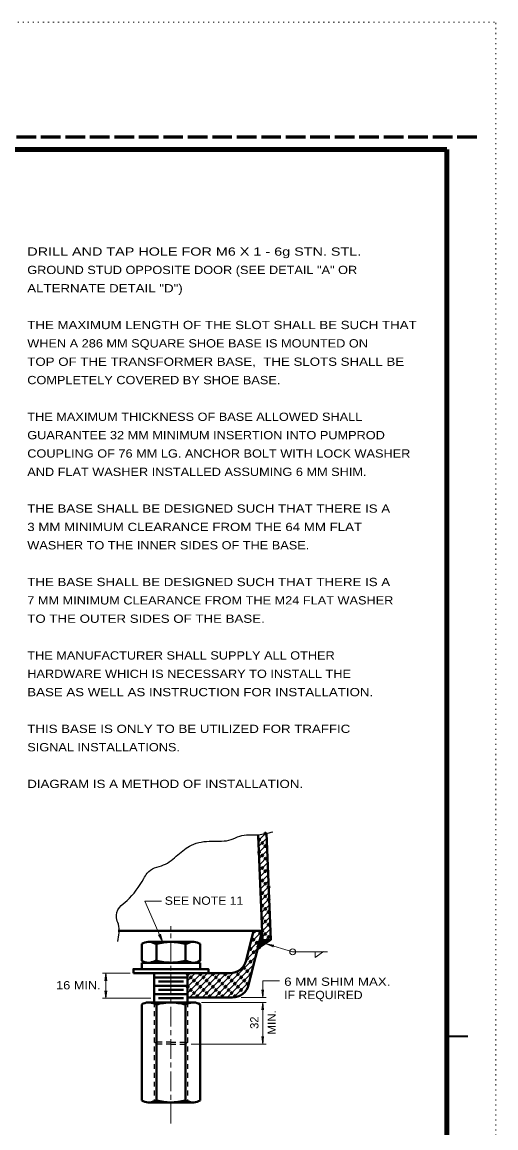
# Model space of a CAD drawing. Extents: x 312583 to 312854, y 144419 to 144597.
# Drawn here: x 312810 to 312853.5, y 144495.2 to 144596.8 of the extents above; entities that cross this region are included whole.
import ezdxf

# ---------------------------------------------------------------- set-up
doc = ezdxf.new("R2010")
doc.units = 0
doc.header["$LTSCALE"] = 0.3
doc.header["$PDMODE"] = 32
doc.header["$PDSIZE"] = 0.15
for name, pattern in [('DOTTED', [1.5, 0.3, -1.2]), ('LONG_DASH_SHORT_DASH', [9.9, 6, -1.2, 1.5, -1.2]), ('LONG_DASHED', [7.5, 6, -1.5]), ('SHORT_DASHED', [2.7, 1.5, -1.2])]:
    doc.linetypes.add(name, pattern=pattern)
for name, color, linetype, lineweight in [('1', 7, 'Continuous', 40), ('2', 7, 'Continuous', 13), ('62', 7, 'DOTTED', 13), ('63', 7, 'LONG_DASHED', 60)]:
    doc.layers.add(name, color=color, linetype=linetype, lineweight=lineweight)

msp = doc.modelspace()

# ---------------------------------------------------------------- linework, layer by layer
at = {"layer": '1', "lineweight": 158}
msp.add_line((312849, 144423.1446), (312849, 144585.0846), dxfattribs=at)
at = {"layer": '1'}
for p, q in [((312832.0464, 144512.4408), (312831.6554, 144522.0855)), ((312832.8131, 144512.4715), (312832.4144, 144522.2695)), ((312818.7984, 144513.2995), (312832.0234, 144513.2995)), ((312831.2338, 144513.2995), (312830.5438, 144510.5548)), ((312832.0234, 144513.2995), (312830.7814, 144508.3238)), ((312821.5431, 144512.2721), (312823.6438, 144512.2721)), ((312825.7368, 144512.2721), (312823.6438, 144512.2721)), ((312820.9604, 144512.0805), (312820.9604, 144510.5471)), ((312822.3021, 144512.0805), (312822.3021, 144510.5471)), ((312824.9778, 144512.0805), (312824.9778, 144510.5471)), ((312826.3271, 144512.0805), (312826.3271, 144510.5471)), ((312820.9604, 144509.7805), (312820.9604, 144510.3555)), ((312820.9604, 144510.3555), (312823.6438, 144510.3555)), ((312826.3271, 144510.3555), (312823.6438, 144510.3555)), ((312826.3271, 144509.7805), (312826.3271, 144510.3555)), ((312823.6438, 144509.3971), (312820.1938, 144509.3971)), ((312822.1104, 144509.3971), (312822.1104, 144506.7138)), ((312823.6438, 144509.3971), (312827.0938, 144509.3971)), ((312825.1771, 144509.3971), (312825.1771, 144506.7138)), ((312829.0564, 144509.3971), (312827.0938, 144509.3971)), ((312822.1104, 144509.0138), (312823.6438, 144509.0138)), ((312822.1104, 144508.2471), (312823.6438, 144508.2471)), ((312822.4938, 144508.6305), (312823.6438, 144508.6305)), ((312825.1771, 144509.0138), (312823.6438, 144509.0138)), ((312824.7938, 144508.6305), (312823.6438, 144508.6305)), ((312825.1771, 144508.2471), (312823.6438, 144508.2471)), ((312822.1104, 144507.4805), (312823.6438, 144507.4805)), ((312822.4938, 144507.8638), (312823.6438, 144507.8638)), ((312824.7938, 144507.8638), (312823.6438, 144507.8638)), ((312825.1771, 144507.4805), (312823.6438, 144507.4805)), ((312820.9604, 144506.5221), (312820.9604, 144497.7055)), ((312821.5431, 144506.7138), (312823.6438, 144506.7138)), ((312822.3021, 144506.5221), (312822.3021, 144497.7055)), ((312822.4938, 144507.0971), (312823.6438, 144507.0971)), ((312824.7938, 144507.0971), (312823.6438, 144507.0971)), ((312825.7368, 144506.7138), (312823.6438, 144506.7138)), ((312824.9778, 144506.5221), (312824.9778, 144497.7055)), ((312829.2941, 144507.1661), (312825.1771, 144507.1661)), ((312826.3271, 144506.5221), (312826.3271, 144497.7055)), ((312821.5431, 144497.5138), (312823.6438, 144497.5138)), ((312825.7368, 144497.5138), (312823.6438, 144497.5138))]:
    msp.add_line(p, q, dxfattribs=at)
at = {"layer": '1', "lineweight": 13}
for p, q in [((312831.6784, 144521.5795), (312832.3531, 144522.2541)), ((312831.7014, 144521.0275), (312832.4374, 144521.7635)), ((312831.7244, 144520.4755), (312832.4604, 144521.2115)), ((312831.7398, 144519.9235), (312832.4834, 144520.6595)), ((312831.7704, 144519.3638), (312832.5064, 144520.1075)), ((312831.7858, 144518.8118), (312832.5294, 144519.5478)), ((312831.8088, 144518.2521), (312832.5524, 144518.9958)), ((312831.8318, 144517.7001), (312832.5754, 144518.4361)), ((312831.8624, 144517.1481), (312832.5984, 144517.8841)), ((312831.8778, 144516.5961), (312832.6138, 144517.3321)), ((312831.9008, 144516.0365), (312832.6444, 144516.7801)), ((312831.9238, 144515.4845), (312832.6598, 144516.2281)), ((312831.9468, 144514.9325), (312832.6904, 144515.6685)), ((312831.9698, 144514.3728), (312832.7058, 144515.1165)), ((312831.9928, 144513.8208), (312832.7288, 144514.5568)), ((312831.1418, 144512.9468), (312831.4944, 144513.2995)), ((312832.0158, 144513.2688), (312832.7518, 144514.0048)), ((312832.0388, 144512.7168), (312832.7748, 144513.4528)), ((312830.7584, 144511.4135), (312831.8164, 144512.4715)), ((312830.9501, 144512.1801), (312832.0081, 144513.2381)), ((312832.3531, 144512.4485), (312832.7978, 144512.9008)), ((312830.5668, 144510.6391), (312831.6248, 144511.6971)), ((312827.6688, 144507.1661), (312831.4331, 144510.9305)), ((312825.1771, 144507.5495), (312827.0171, 144509.3971)), ((312825.1771, 144508.1321), (312826.4421, 144509.3971)), ((312825.1771, 144508.7071), (312825.8671, 144509.3971)), ((312825.1771, 144509.2821), (312825.2844, 144509.3971)), ((312825.3611, 144507.1661), (312827.5921, 144509.3971)), ((312825.9361, 144507.1661), (312828.1671, 144509.3971)), ((312826.5111, 144507.1661), (312828.7498, 144509.3971)), ((312827.0938, 144507.1661), (312829.3631, 144509.4355)), ((312828.2438, 144507.1661), (312831.2414, 144510.1561)), ((312828.8188, 144507.1661), (312831.0498, 144509.3895)), ((312829.4244, 144507.1891), (312830.8504, 144508.6228))]:
    msp.add_line(p, q, dxfattribs=at)
at = {"layer": '1', "linetype": 'LONG_DASH_SHORT_DASH', "lineweight": 13}
msp.add_line((312823.6438, 144495.5971), (312823.6438, 144513.7288), dxfattribs=at)
at = {"layer": '1', "lineweight": 25}
for p, q in [((312831.6248, 144511.6895), (312832.3838, 144512.4485)), ((312831.6401, 144511.7585), (312832.3301, 144512.4485)), ((312831.6554, 144511.8275), (312832.2764, 144512.4485)), ((312831.6784, 144511.8965), (312832.2228, 144512.4485)), ((312831.6938, 144511.9655), (312832.1691, 144512.4408)), ((312831.7091, 144512.0345), (312832.1154, 144512.4408)), ((312831.7244, 144512.1035), (312832.0618, 144512.4408)), ((312831.7398, 144511.7508), (312832.4374, 144512.4561)), ((312831.7474, 144512.1725), (312832.0464, 144512.4791)), ((312831.7628, 144512.2415), (312832.0464, 144512.5328)), ((312831.7781, 144512.3181), (312832.0464, 144512.5788)), ((312831.8011, 144512.3795), (312832.0464, 144512.6325)), ((312831.8164, 144512.4561), (312832.0388, 144512.6785)), ((312831.8318, 144512.5175), (312832.0388, 144512.7321)), ((312831.8471, 144512.5941), (312832.0388, 144512.7781)), ((312831.8624, 144512.6631), (312832.0388, 144512.8318)), ((312831.8854, 144512.7321), (312832.0311, 144512.8855)), ((312831.8931, 144511.8581), (312832.4911, 144512.4561)), ((312831.9008, 144512.7935), (312832.0311, 144512.9315)), ((312831.9161, 144512.8701), (312832.0311, 144512.9851)), ((312831.9314, 144512.9315), (312832.0311, 144513.0311)), ((312831.9544, 144513.0081), (312832.0311, 144513.0848)), ((312831.9698, 144513.0771), (312832.0311, 144513.1385)), ((312831.9851, 144513.1461), (312832.0234, 144513.1845)), ((312832.0004, 144513.2151), (312832.0234, 144513.2381)), ((312832.0158, 144513.2841), (312832.0234, 144513.2841)), ((312832.0464, 144511.9578), (312832.5448, 144512.4561)), ((312832.1998, 144512.0651), (312832.5984, 144512.4561)), ((312832.3608, 144512.1648), (312832.6598, 144512.4638)), ((312832.5141, 144512.2721), (312832.7058, 144512.4638)), ((312832.6674, 144512.3718), (312832.7671, 144512.4715))]:
    msp.add_line(p, q, dxfattribs=at)
at = {"layer": '1', "linetype": 'SHORT_DASHED', "lineweight": 25}
for p, q in [((312822.1104, 144506.7138), (312822.1104, 144497.5138)), ((312825.1771, 144506.7138), (312825.1771, 144497.5138)), ((312823.6438, 144503.0721), (312822.1104, 144503.0721)), ((312822.3864, 144502.8805), (312822.1104, 144503.0721)), ((312823.6438, 144502.8805), (312822.3864, 144502.8805)), ((312823.6438, 144503.0721), (312825.1771, 144503.0721)), ((312823.6438, 144502.8805), (312824.9011, 144502.8805)), ((312824.9011, 144502.8805), (312825.1771, 144503.0721))]:
    msp.add_line(p, q, dxfattribs=at)
at = {"layer": '1', "lineweight": 35}
msp.add_line((312849, 144503.6216), (312850.932, 144503.6216), dxfattribs=at)
at = {"layer": '1', "lineweight": 158}
msp.add_lwpolyline([(312616.5, 144423.1446), (312616.5, 144585.0846), (312849, 144585.0846)], dxfattribs=at)
at = {"layer": '1'}
for points in [[(312832.0464, 144512.4408), (312832.8131, 144512.4715), (312831.6171, 144511.6665)], [(312823.6438, 144509.7805), (312820.1938, 144509.7805), (312820.1938, 144509.3971)], [(312823.6438, 144509.7805), (312827.0938, 144509.7805), (312827.0938, 144509.3971)]]:
    msp.add_lwpolyline(points, dxfattribs=at)
for centre, radius, start, end in [((312821.0439, 144509.1699), 3.1689, 66.63635, 78.22986), ((312823.7809, 144506.5549), 5.7189, 91.405, 105.00202), ((312823.5005, 144506.5549), 5.7189, 74.99798, 88.595), ((312826.2375, 144509.1699), 3.1689, 101.77014, 113.36365), ((312821.5783, 144511.1629), 1.1066, 91.66257, 124.1297), ((312825.7031, 144511.1629), 1.1066, 55.8703, 88.33743), ((312821.5783, 144511.4678), 1.1066, 235.8703, 268.33743), ((312821.0439, 144513.4608), 3.1689, 281.77014, 293.36365), ((312823.7809, 144516.0757), 5.7189, 254.99798, 268.595), ((312823.5005, 144516.0757), 5.7189, 271.405, 285.00202), ((312826.2375, 144513.4608), 3.1689, 246.63635, 258.22986), ((312825.7031, 144511.4678), 1.1066, 271.66257, 304.1297), ((312829.0593, 144510.9289), 1.5333, 270, 345.93881), ((312829.2938, 144508.6964), 1.5333, 270, 345.95631), ((312821.5783, 144505.603), 1.1066, 91.66257, 124.1297), ((312821.0439, 144503.61), 3.1689, 66.63635, 78.22986), ((312823.7809, 144500.9951), 5.7189, 91.405, 105.00202), ((312823.5005, 144500.9951), 5.7189, 74.99798, 88.595), ((312826.2375, 144503.61), 3.1689, 101.77014, 113.36365), ((312825.7031, 144505.603), 1.1066, 55.8703, 88.33743), ((312821.5783, 144498.6215), 1.1066, 235.8703, 268.33743), ((312821.0439, 144500.6145), 3.1689, 281.77014, 293.36365), ((312823.7809, 144503.2295), 5.7189, 254.99798, 268.595), ((312823.5005, 144503.2295), 5.7189, 271.405, 285.00202), ((312826.2375, 144500.6145), 3.1689, 246.63635, 258.22986), ((312825.7031, 144498.6215), 1.1066, 271.66257, 304.1297)]:
    msp.add_arc(centre, radius, start, end, dxfattribs=at)
at = {"layer": '1', "lineweight": 25}
msp.add_spline([(312818.7601, 144512.3181), (312818.8138, 144513.8898), (312818.6298, 144514.4955), (312818.9058, 144515.4308), (312819.6111, 144516.0825), (312821.1444, 144518.0835), (312821.4741, 144518.5971), (312822.1258, 144519.0648), (312822.9691, 144519.3408), (312824.2724, 144520.2761), (312825.5298, 144521.1655), (312827.3928, 144521.5335), (312829.1638, 144521.6715), (312829.9611, 144522.0011), (312831.6708, 144522.1161), (312833.0048, 144522.3998)], degree=3, dxfattribs=at)
at = {"layer": '1'}
for p in [(312831.7474, 144521.6561), (312832.0388, 144521.3648), (312832.3224, 144522.2311), (312831.7474, 144520.4985), (312832.3224, 144521.0735), (312832.0388, 144520.2148), (312832.3224, 144519.9235), (312832.0388, 144519.0571), (312832.3224, 144518.7735), (312832.0388, 144517.9071), (312832.3224, 144517.6158), (312832.6138, 144517.3321), (312832.0388, 144516.7495), (312832.3224, 144516.4581), (312832.0388, 144515.5995), (312832.3224, 144515.3081), (312832.6138, 144516.1745), (312832.0388, 144514.4418), (312832.6138, 144515.0168), (312832.0388, 144513.2918), (312832.3224, 144514.1581), (312832.6138, 144513.8668), (312831.2491, 144512.4715), (312831.8241, 144513.0541), (312832.3224, 144513.0005), (312832.6138, 144512.7168), (312830.9578, 144511.6128), (312831.2491, 144511.3215), (312831.5328, 144512.1878), (312831.6631, 144511.8275), (312831.6861, 144511.8045), (312831.7091, 144511.7815), (312831.7398, 144511.7508), (312830.6664, 144510.7465), (312830.9578, 144510.4551), (312825.1924, 144509.2975), (312826.3424, 144509.2975), (312827.5001, 144509.2975), (312828.6501, 144509.2975), (312829.8078, 144509.2975), (312830.3828, 144509.8801), (312830.6664, 144509.5888), (312830.9578, 144509.2975), (312825.1924, 144508.1475), (312825.4761, 144509.0138), (312825.7674, 144508.7225), (312826.0588, 144508.4388), (312826.3424, 144508.1475), (312826.6338, 144509.0138), (312826.9251, 144508.7225), (312827.2088, 144508.4388), (312827.5001, 144508.1475), (312827.7838, 144509.0138), (312828.0751, 144508.7225), (312828.3664, 144508.4388), (312828.6501, 144508.1475), (312828.9414, 144509.0138), (312829.2251, 144508.7225), (312829.5164, 144508.4388), (312829.8078, 144508.1475), (312830.0914, 144509.0138), (312830.3828, 144508.7225), (312830.6664, 144508.4388), (312825.4761, 144507.8561), (312825.7674, 144507.5725), (312826.0588, 144507.2811), (312826.6338, 144507.8561), (312826.9251, 144507.5725), (312827.2088, 144507.2811), (312827.7838, 144507.8561), (312828.0751, 144507.5725), (312828.3664, 144507.2811), (312828.9414, 144507.8561), (312829.2251, 144507.5725), (312829.5164, 144507.2811), (312830.0914, 144507.8561)]:
    msp.add_point(p, dxfattribs=at)
at = {"layer": '2'}
for p, q in [((312821.2364, 144516.0211), (312822.7698, 144516.0211)), ((312822.8694, 144512.3181), (312821.2364, 144516.0211)), ((312822.5091, 144512.9238), (312822.6778, 144512.7551)), ((312822.8694, 144512.3181), (312822.5091, 144512.9238)), ((312822.6701, 144512.9928), (312822.6778, 144512.7551)), ((312822.8694, 144512.3181), (312822.6701, 144512.9928)), ((312832.3991, 144512.0805), (312834.8218, 144511.3598)), ((312832.3991, 144512.0805), (312833.0431, 144511.8045)), ((312832.3991, 144512.0805), (312833.0891, 144511.9655)), ((312833.0891, 144511.9655), (312832.8514, 144511.9501)), ((312833.0431, 144511.8045), (312832.8514, 144511.9501)), ((312834.8218, 144511.3598), (312838.0418, 144511.3598)), ((312817.3571, 144509.3971), (312819.8871, 144509.3971)), ((312817.6638, 144509.3971), (312817.5794, 144508.6995)), ((312817.6638, 144507.0971), (312817.6638, 144509.3971)), ((312817.6638, 144509.3971), (312817.7558, 144508.6995)), ((312817.5794, 144508.6995), (312817.6638, 144508.9218)), ((312817.7558, 144508.6995), (312817.6638, 144508.9218)), ((312832.0771, 144507.1661), (312832.0771, 144508.6995)), ((312833.6104, 144508.6995), (312832.0771, 144508.6995)), ((312817.5794, 144507.7871), (312817.6638, 144507.5648)), ((312817.6638, 144507.0971), (312817.5794, 144507.7871)), ((312817.7558, 144507.7871), (312817.6638, 144507.5648)), ((312817.6638, 144507.0971), (312817.7558, 144507.7871)), ((312831.9851, 144507.8561), (312832.0771, 144507.6338)), ((312832.0771, 144507.1661), (312831.9851, 144507.8561)), ((312832.1614, 144507.8561), (312832.0771, 144507.6338)), ((312832.0771, 144507.1661), (312832.1614, 144507.8561)), ((312817.3571, 144507.0971), (312821.8038, 144507.0971)), ((312826.4651, 144506.7138), (312832.3838, 144506.7138)), ((312830.0838, 144507.1661), (312832.3838, 144507.1661)), ((312832.0771, 144506.7138), (312831.9851, 144506.0161)), ((312831.9851, 144506.0161), (312832.0771, 144506.2385)), ((312832.0771, 144502.8805), (312832.0771, 144506.7138)), ((312832.0771, 144506.7138), (312832.1614, 144506.0161)), ((312832.1614, 144506.0161), (312832.0771, 144506.2385)), ((312831.9851, 144503.5705), (312832.0771, 144503.3481)), ((312832.0771, 144502.8805), (312831.9851, 144503.5705)), ((312832.1614, 144503.5705), (312832.0771, 144503.3481)), ((312832.0771, 144502.8805), (312832.1614, 144503.5705)), ((312825.5068, 144502.8805), (312832.3838, 144502.8805))]:
    msp.add_line(p, q, dxfattribs=at)
msp.add_lwpolyline([(312837.6584, 144511.3751), (312836.9071, 144510.8231), (312836.9071, 144511.3598)], dxfattribs=at)
msp.add_circle((312834.8248, 144511.3583), 0.2724, dxfattribs=at)
at = {"layer": '62'}
msp.add_line((312601.2, 144596.7846), (312853.5, 144596.7846), dxfattribs=at)
msp.add_lwpolyline([(312601.2, 144418.5846), (312853.5, 144418.5846), (312853.5, 144596.7846)], dxfattribs=at)
at = {"layer": '63'}
msp.add_line((312851.75, 144586.2246), (312583.526, 144586.2246), dxfattribs=at)

# ---------------------------------------------------------------- texts
at = {"layer": '2'}
for s, width, p in [('DRILL AND TAP HOLE FOR M6 X 1 - 6g STN. STL.  ', 1.3, (312810.4431, 144575.3222)), ('GROUND STUD OPPOSITE DOOR (SEE DETAIL "A" OR', 1.15, (312810.4431, 144573.6356)), ('ALTERNATE DETAIL "D") ', 1.2, (312810.4431, 144571.9489)), ('THE MAXIMUM LENGTH OF THE SLOT SHALL BE SUCH THAT ', 1.2, (312810.4431, 144568.5756)), ('WHEN A 286 MM SQUARE SHOE BASE IS MOUNTED ON ', 1.15, (312810.4431, 144566.8889)), ('TOP OF THE TRANSFORMER BASE,  THE SLOTS SHALL BE ', 1.2, (312810.4431, 144565.2022)), ('COMPLETELY COVERED BY SHOE BASE. ', 1.15, (312810.4431, 144563.5156)), ('THE MAXIMUM THICKNESS OF BASE ALLOWED SHALL ', 1.15, (312810.4431, 144560.1422)), ('GUARANTEE 32 MM MINIMUM INSERTION INTO PUMPROD', 1.15, (312810.4431, 144558.4556)), ('COUPLING OF 76 MM LG. ANCHOR BOLT WITH LOCK WASHER ', 1.15, (312810.4431, 144556.7689)), ('AND FLAT WASHER INSTALLED ASSUMING 6 MM SHIM.', 1.15, (312810.4431, 144555.0822)), ('THE BASE SHALL BE DESIGNED SUCH THAT THERE IS A  ', 1.2, (312810.4431, 144551.7089)), ('3 MM MINIMUM CLEARANCE FROM THE 64 MM FLAT', 1.2, (312810.4431, 144550.0222)), ('WASHER TO THE INNER SIDES OF THE BASE.', 1.15, (312810.4431, 144548.3356)), ('THE BASE SHALL BE DESIGNED SUCH THAT THERE IS A  ', 1.2, (312810.4431, 144544.9622)), ('7 MM MINIMUM CLEARANCE FROM THE M24 FLAT WASHER', 1.15, (312810.4431, 144543.2756)), ('TO THE OUTER SIDES OF THE BASE. ', 1.2, (312810.4431, 144541.5889)), ('THE MANUFACTURER SHALL SUPPLY ALL OTHER ', 1.15, (312810.4431, 144538.2156)), ('HARDWARE WHICH IS NECESSARY TO INSTALL THE', 1.15, (312810.4431, 144536.5289)), ('BASE AS WELL AS INSTRUCTION FOR INSTALLATION. ', 1.2, (312810.4431, 144534.8422)), ('THIS BASE IS ONLY TO BE UTILIZED FOR TRAFFIC', 1.2, (312810.4431, 144531.4689)), ('SIGNAL INSTALLATIONS.', 1.15, (312810.4431, 144529.7822)), ('DIAGRAM IS A METHOD OF INSTALLATION.', 1.2, (312810.4431, 144526.4089)), ('SEE NOTE 11', 1.1, (312823.0764, 144515.6821)), ('16 MIN.', 1.15, (312813.0935, 144507.9102)), ('6 MM SHIM MAX.', 1.2, (312834.0495, 144508.2369)), ('IF REQUIRED', 1.1, (312834.0495, 144507.0169))]:
    msp.add_text(s, height=0.76, dxfattribs=dict(at, width=width)).set_placement(p)
msp.add_text('32', height=0.76, rotation=90, dxfattribs=at).set_placement((312831.6848, 144504.2829))
at = {"layer": '2', "width": 1.05}
msp.add_text('MIN.', height=0.76, rotation=90, dxfattribs=at).set_placement((312833.2793, 144503.751))

doc.saveas('drawing.dxf')
